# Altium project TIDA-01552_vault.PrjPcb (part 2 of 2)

## Sheet TIDA-01552_pg-5_OP_Connector.SchDoc
size 431 x 279 mm; Date: Not shown in title block; ApprovedBy: Not shown in title block; CheckedBy: Not shown in title block; Author: Not shown in title block; CompanyName: Not shown in title block; Engineer: Not shown in title block; Organization: Not shown in title block; Address1: Not shown in title block; Address2: Not shown in title block; Address3: Not shown in title block; Address4: Not shown in title block; DocumentNumber: 6; Revision: Use project parameter SCH_Rev; SheetNumber: 6; SheetTotal: 7; PageSetup: Record=PageOptions¦CenterHorizontal=True¦CenterVertical=True¦PrintScale=1.00¦XCorrection=1.00¦YCorrection=1.00¦PrintKind=0¦BorderSize=5000000¦LeftOffset=0¦BottomOffset=0¦Orientation=2¦PaperLength=1000¦PaperWidth=1000¦Scale=100¦PaperSource=15¦PrintQuality=600¦MediaType=1¦DitherType=10¦PaperKind=Letter¦PrintScaleMode=1
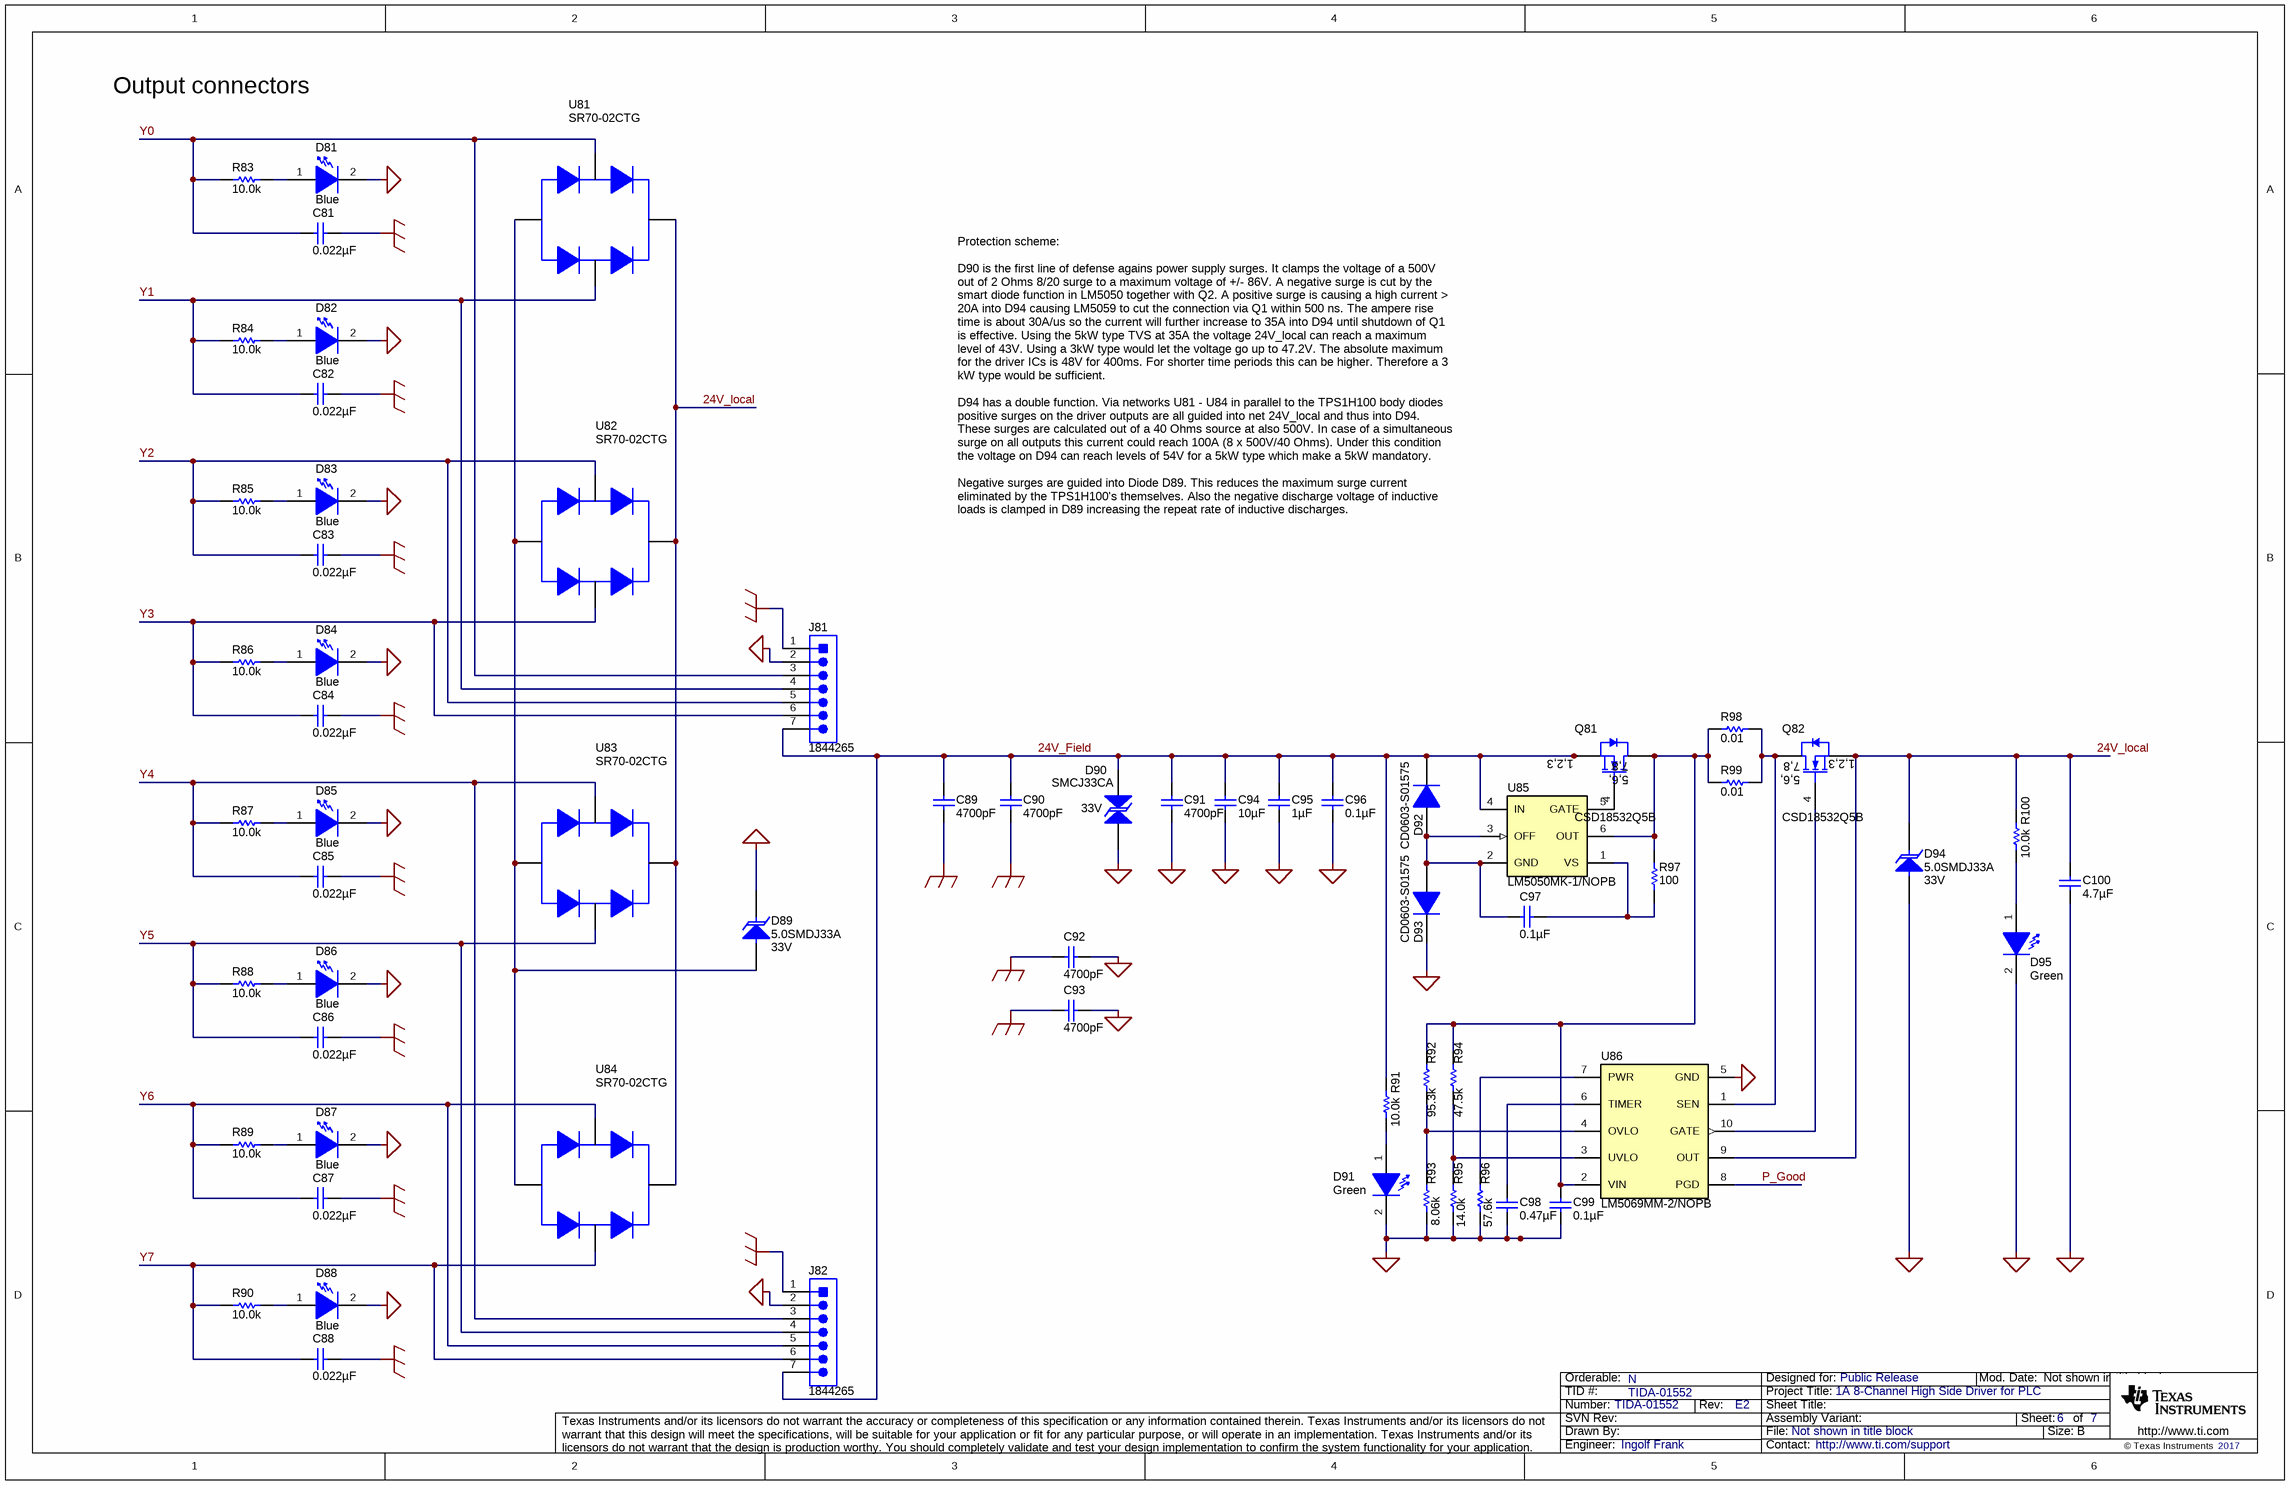
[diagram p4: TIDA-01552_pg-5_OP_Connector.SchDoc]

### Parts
C81  ValueDisplayed: 0.022µF  [0603]  (hidden comment: C1608X7R2A223K080AA)
C82  ValueDisplayed: 0.022µF  [0603]  (hidden comment: C1608X7R2A223K080AA)
C83  ValueDisplayed: 0.022µF  [0603]  (hidden comment: C1608X7R2A223K080AA)
C84  ValueDisplayed: 0.022µF  [0603]  (hidden comment: C1608X7R2A223K080AA)
C85  ValueDisplayed: 0.022µF  [0603]  (hidden comment: C1608X7R2A223K080AA)
C86  ValueDisplayed: 0.022µF  [0603]  (hidden comment: C1608X7R2A223K080AA)
C87  ValueDisplayed: 0.022µF  [0603]  (hidden comment: C1608X7R2A223K080AA)
C88  ValueDisplayed: 0.022µF  [0603]  (hidden comment: C1608X7R2A223K080AA)
C89  ValueDisplayed: 4700pF  [1812]  (hidden comment: 1812GC472KA1)
C90  ValueDisplayed: 4700pF  [1812]  (hidden comment: 1812GC472KA1)
C91  ValueDisplayed: 4700pF  [0805_HV]  (hidden comment: 08051C472KAT2A)
C92  ValueDisplayed: 4700pF  [1812]  (hidden comment: 1812GC472KA1)
C93  ValueDisplayed: 4700pF  [1812]  (hidden comment: 1812GC472KA1)
C94  ValueDisplayed: 10µF  [2220_250]  (hidden comment: C5750X7S2A106M230KB)
C95  ValueDisplayed: 1µF  [0805L]  (hidden comment: C2012X7S2A105K125AB)
C96  ValueDisplayed: 0.1µF  [0603]  (hidden comment: GRM188R72A104KA35D)
C97  ValueDisplayed: 0.1µF  [0603]  (hidden comment: GRM188R72A104KA35D)
C98  ValueDisplayed: 0.47µF  [0603]  (hidden comment: GRM188R71E474KA12D)
C99  ValueDisplayed: 0.1µF  [0603]  (hidden comment: GRM188R72A104KA35D)
C100  ValueDisplayed: 4.7µF  [1210_220]  (hidden comment: C3225X7S2A475K200AB)
D81  value Blue  [LB Q39G_BLUE]  (hidden comment: LB Q39G-L2N2-35-1)
D82  value Blue  [LB Q39G_BLUE]  (hidden comment: LB Q39G-L2N2-35-1)
D83  value Blue  [LB Q39G_BLUE]  (hidden comment: LB Q39G-L2N2-35-1)
D84  value Blue  [LB Q39G_BLUE]  (hidden comment: LB Q39G-L2N2-35-1)
D85  value Blue  [LB Q39G_BLUE]  (hidden comment: LB Q39G-L2N2-35-1)
D86  value Blue  [LB Q39G_BLUE]  (hidden comment: LB Q39G-L2N2-35-1)
D87  value Blue  [LB Q39G_BLUE]  (hidden comment: LB Q39G-L2N2-35-1)
D88  value Blue  [LB Q39G_BLUE]  (hidden comment: LB Q39G-L2N2-35-1)
D89  5.0SMDJ33A  value 33V  [SMC]
D90  SMCJ33CA  value 33V  [SMC]
D91  value Green  [LED_LTST-C190_G]  (hidden comment: LTST-C190KGKT)
D92  CD0603-S01575  [Diode_0603]
D93  CD0603-S01575  [Diode_0603]
D94  5.0SMDJ33A  value 33V  [SMC]
D95  value Green  [LED_LTST-C190_G]  (hidden comment: LTST-C190KGKT)
J81  1844265  [Phoenix_1844265]
J82  1844265  [Phoenix_1844265]
Q81  CSD18532Q5B  [DNK0008A]
Q82  CSD18532Q5B  [DNK0008A]
R83  value 10.0k  [0603]  (hidden comment: CRCW060310K0FKEA)
R84  value 10.0k  [0603]  (hidden comment: CRCW060310K0FKEA)
R85  value 10.0k  [0603]  (hidden comment: CRCW060310K0FKEA)
R86  value 10.0k  [0603]  (hidden comment: CRCW060310K0FKEA)
R87  value 10.0k  [0603]  (hidden comment: CRCW060310K0FKEA)
R88  value 10.0k  [0603]  (hidden comment: CRCW060310K0FKEA)
R89  value 10.0k  [0603]  (hidden comment: CRCW060310K0FKEA)
R90  value 10.0k  [0603]  (hidden comment: CRCW060310K0FKEA)
R91  value 10.0k  [0603]  (hidden comment: CRCW060310K0FKEA)
R92  value 95.3k  [0603_HV]  (hidden comment: CRCW060395K3FKEA)
R93  value 8.06k  [0603_HV]  (hidden comment: CRCW06038K06FKEA)
R94  value 47.5k  [0603_HV]  (hidden comment: CRCW060347K5FKEA)
R95  value 14.0k  [0603_HV]  (hidden comment: CRCW060314K0FKEA)
R96  value 57.6k  [0603_HV]  (hidden comment: CRCW060357K6FKEA)
R97  value 100  [0603]  (hidden comment: CRCW0603100RFKEA)
R98  value 0.01  [1206]  (hidden comment: WSLP1206R0100FEA)
R99  value 0.01  [1206]  (hidden comment: WSLP1206R0100FEA)
R100  value 10.0k  [0603]  (hidden comment: CRCW060310K0FKEA)
U81  SR70-02CTG  [SOT-143-4]
U82  SR70-02CTG  [SOT-143-4]
U83  SR70-02CTG  [SOT-143-4]
U84  SR70-02CTG  [SOT-143-4]
U85  LM5050MK-1/NOPB  [DDC0006A_N]
U86  LM5069MM-2/NOPB  [MUB10A_N]

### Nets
24V_local: C100.1 D94.1(K) Q82.1(S) Q82.2(S) Q82.3(S) R100.1 U81.4(VCC) U82.4(VCC) U83.4(VCC) U84.4(VCC) U86.9(OUT)
GND_EARTH: C81.2 C82.2 C83.2 C84.2 C85.2 C86.2 C87.2 C88.2 C89.2 C90.2 C92.2 C93.2 J81.1 J82.1
GND_SIGNAL: C91.2 C92.1 C93.1 C94.2 C95.2 C96.2 C98.2 C99.2 C100.2 D81.2(K) D82.2(K) D83.2(K) D84.2(K) D85.2(K) D86.2(K) D87.2(K) D88.2(K) D89.1(K) D90.2 D91.2(K) D93.1(K) D94.2(A) D95.2(K) J81.2 J82.2 R93.1 R95.1 R96.1 U86.5(GND)
24V_Field: C89.1 C90.1 C91.1 C94.1 C95.1 C96.1 D90.1 D92.1(K) J81.7 J82.7 Q81.1(S) Q81.2(S) Q81.3(S) R91.1 U85.4(IN)
P_Good: U86.8(PGD)
Y0: C81.1 J81.3 R83.2 U81.2(I/O)
Y1: C82.1 J81.4 R84.2 U81.3(I/O)
Y2: C83.1 J81.5 R85.2 U82.2(I/O)
Y3: C84.1 J81.6 R86.2 U82.3(I/O)
Y4: C85.1 J82.3 R87.2 U83.2(I/O)
Y5: C86.1 J82.4 R88.2 U83.3(I/O)
Y6: C87.1 J82.5 R89.2 U84.2(I/O)
Y7: C88.1 J82.6 R90.2 U84.3(I/O)
NetC97_1: C97.1 R97.1 U85.1(VS)
NetC97_2: C97.2 D92.2(A) D93.2(A) U85.2(GND) U85.3(OFF)
NetC98_1: C98.1 U86.6(TIMER)
NetC99_1: C99.1 Q81.5(D) Q81.6(D) Q81.7(D) Q81.8(D) Q81.9(D) R92.2 R94.2 R97.2 R98.1 R99.1 U85.6(OUT) U86.2(VIN)
NetD81_1: D81.1(A) R83.1
NetD82_1: D82.1(A) R84.1
NetD83_1: D83.1(A) R85.1
NetD84_1: D84.1(A) R86.1
NetD85_1: D85.1(A) R87.1
NetD86_1: D86.1(A) R88.1
NetD87_1: D87.1(A) R89.1
NetD88_1: D88.1(A) R90.1
NetD89_2: D89.2(A) U81.1(GND) U82.1(GND) U83.1(GND) U84.1(GND)
NetD91_1: D91.1(A) R91.2
NetD95_1: D95.1(A) R100.2
NetQ81_4: Q81.4(G) U85.5(GATE)
NetQ82_4: Q82.4(G) U86.10(GATE)
NetQ82_5: Q82.5(D) Q82.6(D) Q82.7(D) Q82.8(D) Q82.9(D) R98.2 R99.2 U86.1(SEN)
NetR92_1: R92.1 R93.2 U86.4(OVLO)
NetR94_1: R94.1 R95.2 U86.3(UVLO)
NetR96_2: R96.2 U86.7(PWR)

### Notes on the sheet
- Output connectors
- Protection scheme:
  D90 is the first line of defense agains power supply surges. It clamps the voltage of a 500V out of 2 Ohms 8/20 surge to a maximum voltage of +/- 86V. A negative surge is cut by the smart diode function in LM5050 together with Q2. A positive surge is causing a high current > 20A into D94 causing LM5059 to cut the connection via Q1 within 500 ns. The ampere rise time is about 30A/us so the current will further increase to 35A into D94 until shutdown of Q1 is effective. Using the 5kW type TVS at 35A the voltage 24V_local can reach a maximum level of 43V. Using a 3kW type would let the voltage go up to 47.2V. The absolute maximum for the driver ICs is 48V for 400ms. For shorter time periods this can be higher. Therefore a 3 kW type would be sufficient.
  D94 has a double function. Via networks U81 - U84 in parallel to the TPS1H100 body diodes positive surges on the driver outputs are all guided into net 24V_local and thus into D94. These surges are calculated out of a 40 Ohms source at also 500V. In case of a simultaneous surge on all outputs this current could reach 100A (8 x 500V/40 Ohms). Under this condition the voltage on D94 can reach levels of 54V for a 5kW type which make a 5kW mandatory.
  Negative surges are guided into Diode D89. This reduces the maximum surge current eliminated by the TPS1H100's themselves. Also the negative discharge voltage of inductive loads is clamped in D89 increasing the repeat rate of inductive discharges.

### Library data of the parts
C81-C88 = C1608X7R2A223K080AA: CAP, CERM, 0.022 µF, 100 V,+/- 10%, X7R, 0603; Manufacturer: TDK; Polarized: N; CompType: Capacitor; Value: 0.022uF; U/M: EA; Cap_F: 0.000000022; Tolerance_%: 10; ESR_ohm: 0.037; Value1: 0.037 ohm; VDC_V: 100; Value2: 100V; TaMin_C: -55; TaMax_C: 125; SizeArea_mm2: 1.28; SizeAreaWB_mm2: 4.68; SizeX_mm: 1.6; SizeY_mm: 0.8; SizeZ_mm: 1; AEC Category: Q200; Green_Lifecycle: Active; Green_REACh: Passed
C89 C90 C92 C93 = 1812GC472KA1: CAP, CERM, 4700 pF, 2000 V, +/- 10%, X7R, 1812; Manufacturer: AVX; Polarized: N; CompType: Capacitor; Value: 4700pF; U/M: EA; Cap_F: 0.0000000047; Tolerance_%: 10; Value1: Unknown; VDC_V: 2000; Value2: 2000V; TaMin_C: -55; TaMax_C: 125
C91 = 08051C472KAT2A: CAP, CERM, 4700 pF, 100 V,+/- 10%, X7R, 0805; Manufacturer: AVX; Polarized: N; CompType: Capacitor; Value: 4700pF; U/M: EA; Cap_F: 0.0000000047; Tolerance_%: 10; ESR_ohm: 0.119; Value1: 0.119 ohm; VDC_V: 100; Value2: 100V; TaMin_C: -55; TaMax_C: 125; Cap_Case: 0805; SizeArea_mm2: 2.5; SizeAreaWB_mm2: 6.75; SizeX_mm: 2; SizeY_mm: 1.25; SizeZ_mm: 1.45; AEC Category: Q200; Green_Lifecycle: Active; Green_REACh: Passed
C94 = C5750X7S2A106M230KB: CAP, CERM, 10 µF, 100 V,+/- 20%, X7S, 2220; Manufacturer: TDK; Polarized: N; CompType: Capacitor; Value: 10uF; U/M: EA; Cap_F: 0.00001; Tolerance_%: 20; ESR_ohm: 0.005; Value1: 0.005 ohm; VDC_V: 100; Value2: 100V; IRMS_A: 6.45; TaMin_C: -55; TaMax_C: 125; Cap_Case: 2220; SizeArea_mm2: 28.5; SizeAreaWB_mm2: 53.9; SizeX_mm: 5.7; SizeY_mm: 5; SizeZ_mm: 2.5; AEC Category: Q200; Green_Lifecycle: Active; Green_REACh: Passed
C95 = C2012X7S2A105K125AB: CAP, CERM, 1 µF, 100 V,+/- 10%, X7S, 0805; Manufacturer: TDK; Polarized: N; CompType: Capacitor; Value: 1uF; U/M: EA; Cap_F: 0.000001; Tolerance_%: 10; ESR_ohm: 0.008255; Value1: 0.008255 ohm; VDC_V: 100; Value2: 100V; IRMS_A: 2.27442; TaMin_C: -55; TaMax_C: 125; Cap_Case: 0805; SizeArea_mm2: 2.5; SizeAreaWB_mm2: 6.75; SizeX_mm: 2; SizeY_mm: 1.25; SizeZ_mm: 1.45; AEC Category: Q200; Green_Lifecycle: Active; Green_REACh: Passed
C96 C97 C99 = GRM188R72A104KA35D: CAP, CERM, 0.1 µF, 100 V, +/- 10%, X7R, 0603; Manufacturer: MuRata; Polarized: N; CompType: Capacitor; Value: 0.1uF; U/M: EA; Cap_F: 0.0000001; Tolerance_%: 10; Value1: Unknown; VDC_V: 100; Value2: 100V; TaMin_C: -55; TaMax_C: 125
C98 = GRM188R71E474KA12D: CAP, CERM, 0.47 µF, 25 V, +/- 10%, X7R, 0603; Manufacturer: MuRata; Polarized: N; CompType: Capacitor; Value: 0.47uF; Cap_F: 0.00000047; Tolerance_%: 10; VDC_V: 25; Value2: 25V; U/M: EA; Value1: Unknown; TaMin_C: -55; TaMax_C: 125
C100 = C3225X7S2A475K200AB: CAP, CERM, 4.7 µF, 100 V,+/- 10%, X7S, 1210; Manufacturer: TDK; Polarized: N; CompType: Capacitor; Value: 4.7uF; U/M: EA; Cap_F: 0.0000047; Tolerance_%: 10; ESR_ohm: 0.004236; Value1: 0.004236 ohm; VDC_V: 100; Value2: 100V; IRMS_A: 3.57337; TaMin_C: -55; TaMax_C: 125; Cap_Case: 1210; SizeArea_mm2: 8; SizeAreaWB_mm2: 14.7; SizeX_mm: 3.2; SizeY_mm: 2.5; SizeZ_mm: 2.2; AEC Category: Q200; Green_Lifecycle: Active; Green_REACh: Passed
D81-D88 = LB Q39G-L2N2-35-1: LED, Blue, SMD; Manufacturer: OSRAM; Vf_V: 2.85; Value2: 2.85V; Io_A: 0.15; Tjmax_C: 95; Value1: W; U/M: EA
D89 D94 = 5.0SMDJ33A: Diode, TVS, Uni, 33 V, 5000 W, SMC; Manufacturer: Littelfuse; U/M: EA; Power_W: 6.5; Vr_V: 33; Value1: 6.5W; RJA_CperW: 75
D90 = SMCJ33CA: Diode, TVS, Bi, 33V, 1500W, SMC; Manufacturer: Bourns; U/M: EA; Power_W: 1500; Vr_V: 33
D91 D95 = LTST-C190KGKT: LED, Green, SMD; Manufacturer: Lite-On; Type: AlInGaP; Vf_V: 2; Value2: 2V; Io_A: 0.03; Tjmax_C: 85; Value1: W; U/M: EA
D92 D93 = CD0603-S01575: Diode, Switching, 100 V, 0.15 A, 0603 Diode; Manufacturer: Bourns; U/M: EA; Vf_V: 1; Value: 100V; Value1: 0.15A; Value2: 1V; Io_A: 0.15; Vr_V: 100; TJmax_C: 125
J81 J82 = 1844265: Header (Shrouded), 3.5 mm, 7x1, R/A, TH; Manufacturer: Phoenix Contact; Alternate PartNumber: MC 1,5/ 7-G-3,5; SymbolCreator: a0411947; U/M: EA
Q81 Q82 = CSD18532Q5B: MOSFET, N-CH, 60 V, 172 A, DNK0008A (VSON-CLIP-8); Manufacturer: Texas Instruments; Alternate Manufacturer: None; U/M: EA; ChType: N; Value: 60V; VdsMax_V: 60; Value1: 3.3 ohm; Rdson45_ohm: 3.3; Value2: 27 nC; QgTyp_nC: 27; Vgs_V: 1.6; IdsMax_A: 172; SizeAreaWB_mm2: 56; SizeArea_mm2: 30; SizeX_mm: 6; SizeY_mm: 5; SizeZ_mm: 1; AEC Category: Q101
R83-R91 R100 = CRCW060310K0FKEA: RES, 10.0k ohm, 1%, 0.1W, 0603; Manufacturer: Vishay-Dale; CompType: Resistor; Res_ohm: 10000; Value_Code: 10k0; Tolerance_%: 1; Power_W: 0.1; VDC_V: 75; TempCo: 100 ppm/C; EIA_Code: E96; U/M: EA
R92 = CRCW060395K3FKEA: RES, 95.3k ohm, 1%, 0.1W, 0603; Manufacturer: Vishay-Dale; CompType: Resistor; Res_ohm: 95300; Value_Code: 95k3; Tolerance_%: 1; Power_W: 0.1; VDC_V: 75; TempCo: 100 ppm/C; EIA_Code: E96; U/M: EA
R93 = CRCW06038K06FKEA: RES, 8.06k ohm, 1%, 0.1W, 0603; Manufacturer: Vishay-Dale; CompType: Resistor; Res_ohm: 8060; Value_Code: 8k06; Tolerance_%: 1; Power_W: 0.1; VDC_V: 75; TempCo: 100 ppm/C; EIA_Code: E96; U/M: EA
R94 = CRCW060347K5FKEA: RES, 47.5k ohm, 1%, 0.1W, 0603; Manufacturer: Vishay-Dale; CompType: Resistor; Res_ohm: 47500; Value_Code: 47k5; Tolerance_%: 1; Power_W: 0.1; VDC_V: 75; TempCo: 100 ppm/C; EIA_Code: E96; U/M: EA
R95 = CRCW060314K0FKEA: RES, 14.0k ohm, 1%, 0.1W, 0603; Manufacturer: Vishay-Dale; CompType: Resistor; Res_ohm: 14000; Value_Code: 14k0; Tolerance_%: 1; Power_W: 0.1; VDC_V: 75; TempCo: 100 ppm/C; EIA_Code: E96; U/M: EA
R96 = CRCW060357K6FKEA: RES, 57.6k ohm, 1%, 0.1W, 0603; Manufacturer: Vishay-Dale; CompType: Resistor; Res_ohm: 57600; Value_Code: 57k6; Tolerance_%: 1; Power_W: 0.1; VDC_V: 75; TempCo: 100 ppm/C; EIA_Code: E96; U/M: EA
R97 = CRCW0603100RFKEA: RES, 100 ohm, 1%, 0.1W, 0603; Manufacturer: Vishay-Dale; CompType: Resistor; Value_Code: 100R; Tolerance_%: 1; Power_W: 0.1; VDC_V: 75; TempCo: 100 ppm/C; EIA_Code: E96; U/M: EA
R98 R99 = WSLP1206R0100FEA: RES, 0.01 ohm, 1%, 1W, 1206; Manufacturer: Vishay-Dale; CompType: Resistor; Value_Code: R010; Tolerance_%: 1; TempCo: 75 ppm/C; EIA_Code: E96; U/M: EA
U81-U84 = SR70-02CTG: ESD Suppressor Diode Arrays, 70V, SMD; Manufacturer: Littelfuse; SymbolCreator: Altium; CompType: ESD Diode Array
U85 = LM5050MK-1/NOPB: LM5050-1 High Side OR-ing FET Controller, DDC0006A; Alternate Manufacturer: None; Manufacturer: Texas Instruments; SymbolCreator: a0411947; CompType: IC; U/M: EA
U86 = LM5069MM-2/NOPB: Positive High Voltage Hot Swap / Inrush Current Controller with Power Limiting, 10-pin MSOP, Pb-Free; Manufacturer: National Semiconductor; PackageTopMarking: ZXTT*SNBB; PowerWise: N; CompType: MiscPower

## Sheet TIDA-01552_TID_Hardware.SchDoc
size 431 x 279 mm; Date: Not shown in title block; ApprovedBy: Not shown in title block; CheckedBy: Not shown in title block; Author: Not shown in title block; CompanyName: Not shown in title block; Engineer: Not shown in title block; Organization: Not shown in title block; Address1: Not shown in title block; Address2: Not shown in title block; Address3: Not shown in title block; Address4: Not shown in title block; DocumentNumber: 7; Revision: Use project parameter SCH_Rev; SheetNumber: 7; SheetTotal: 7; PageSetup: Record=PageOptions¦CenterHorizontal=True¦CenterVertical=True¦PrintScale=1.00¦XCorrection=1.00¦YCorrection=1.00¦PrintKind=0¦BorderSize=5000000¦LeftOffset=0¦BottomOffset=0¦Orientation=2¦PaperLength=1000¦PaperWidth=1000¦Scale=100¦PaperSource=15¦PrintQuality=600¦MediaType=1¦DitherType=10¦PaperKind=Letter¦PrintScaleMode=1
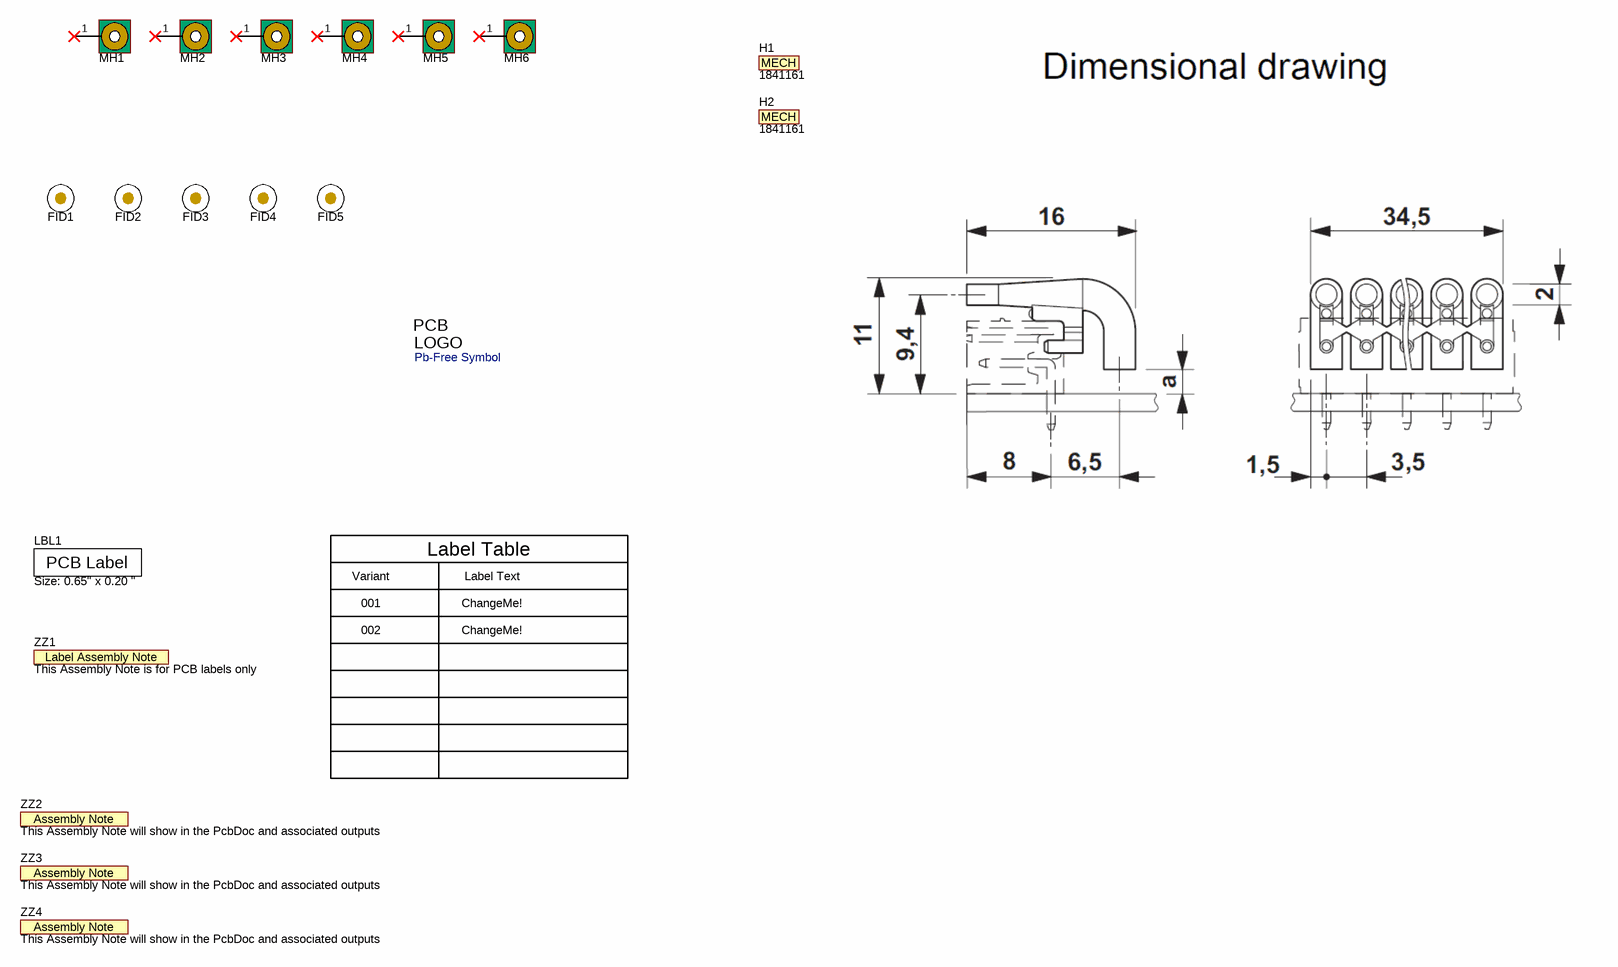
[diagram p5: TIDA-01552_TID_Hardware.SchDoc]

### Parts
FID1  Fiducial  [Fiducial10-20]  (value not drawn)
FID2  Fiducial  [Fiducial10-20]  (value not drawn)
FID3  Fiducial  [Fiducial10-20]  (value not drawn)
FID4  Fiducial  [Fiducial10-20]  (value not drawn)
FID5  Fiducial  [Fiducial10-20]  (value not drawn)
H1  1841161  (mechanical)
H2  1841161  (mechanical)
LBL1  Size: 0.65" x 0.20 "  [Label_650x200]
Logo2  Pb-Free Symbol  [Pb-Free_Overlay_Small]  (no BOM)
MH1  MTG_Pads  [MTGP_4-40_PanHead]  (value not drawn)  (no BOM)
MH2  MTG_Pads  [MTGP_4-40_PanHead]  (value not drawn)  (no BOM)
MH3  MTG_Pads  [MTGP_4-40_PanHead]  (value not drawn)  (no BOM)
MH4  MTG_Pads  [MTGP_4-40_PanHead]  (value not drawn)  (no BOM)
MH5  MTG_Pads  [MTGP_4-40_PanHead]  (value not drawn)  (no BOM)
MH6  MTG_Pads  [MTGP_4-40_PanHead]  (value not drawn)  (no BOM)
ZZ1  This Assembly Note is for PCB labels only  [AssemblyNoteLabel]  (no BOM)
ZZ2  This Assembly Note will show in the PcbDoc and associated outputs  [AssemblyNote]  (no BOM)
ZZ3  This Assembly Note will show in the PcbDoc and associated outputs  [AssemblyNote]  (no BOM)
ZZ4  This Assembly Note will show in the PcbDoc and associated outputs  [AssemblyNote]  (no BOM)

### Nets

Not connected (* = marked no-connect by the designer): MH1 1*; MH2 1*; MH3 1*; MH4 1*; MH5 1*; MH6 1*

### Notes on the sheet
- Variant
- Label Table
- Label Text
- 001
- 002
- ChangeMe!

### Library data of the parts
FID1-FID5 = Fiducial: Fiducial mark.  There is nothing to buy or mount.; SymbolCreator: codlsc
H1 H2 = 1841161: Fiber optics - MC 1,5/10-LWL 1,5-3,5 for Phoenix connectors; Manufacturer: Phoenix Contact; SymbolCreator: codlsc; CompType: Filber Optics
LBL1 = THT-14-423-10: Thermal Transfer Printable Labels, 0.650" W x 0.200" H - 10,000 per roll; Manufacturer: Brady; SymbolCreator: a0412235; CompType: Label
Logo2 = Pb-Free: SymbolCreator: a0412235
MH1-MH6 = Mounting Hole (Imperial) with Pads: PCB Mounting Hole; Manufacturer: Any; SymbolCreator: a0412235
ZZ1 = AssemblyNoteLabel: SymbolCreator: a0412235
ZZ2-ZZ4 = AssemblyNote: SymbolCreator: codlsc

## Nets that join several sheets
24V_local: TIDA-01552_pg-2_PSU-ISO (L21.1), TIDA-01552_pg-4_Driver (33 pins), TIDA-01552_pg-5_OP_Connector (11 pins)
+3.3V_iso: TIDA-01552_pg-2_PSU-ISO (10 pins), TIDA-01552_pg-3_MCU (12 pins), TIDA-01552_pg-4_Driver (C63.1 U63.1 U63.9 U63.14)
DGND: TIDA-01552_pg-1_BB_Connector (30 pins), TIDA-01552_pg-2_PSU-ISO (10 pins)
GND_SIGNAL: TIDA-01552_pg-2_PSU-ISO (19 pins), TIDA-01552_pg-3_MCU (15 pins), TIDA-01552_pg-4_Driver (38 pins), TIDA-01552_pg-5_OP_Connector (29 pins)
SYS_5V: TIDA-01552_pg-1_BB_Connector (J2.7 J2.8 S1.1), TIDA-01552_pg-2_PSU-ISO (C31.1 T21.5 U25.2)
VDD_3V3B: TIDA-01552_pg-1_BB_Connector (24 pins), TIDA-01552_pg-2_PSU-ISO (8 pins)
/CS0: TIDA-01552_pg-1_BB_Connector (R6.2), TIDA-01552_pg-2_PSU-ISO (U22.5)
/CS0_iso: TIDA-01552_pg-2_PSU-ISO (R25.1), TIDA-01552_pg-3_MCU (U44.9)
/SDRDY: TIDA-01552_pg-2_PSU-ISO (U21.7), TIDA-01552_pg-3_MCU (U44.18)
/XSDRDY: TIDA-01552_pg-1_BB_Connector (R1.2), TIDA-01552_pg-2_PSU-ISO (R21.1 U26.4)
CSense: TIDA-01552_pg-3_MCU (U44.7), TIDA-01552_pg-4_Driver (C69.1 R81.1 TP64.1)
D0: TIDA-01552_pg-3_MCU (U44.15), TIDA-01552_pg-4_Driver (R63.1)
D1: TIDA-01552_pg-3_MCU (U44.16), TIDA-01552_pg-4_Driver (R64.1)
D2: TIDA-01552_pg-3_MCU (U44.32), TIDA-01552_pg-4_Driver (R68.1)
D3: TIDA-01552_pg-3_MCU (U44.19), TIDA-01552_pg-4_Driver (R69.1)
D4: TIDA-01552_pg-3_MCU (U44.21), TIDA-01552_pg-4_Driver (R73.1)
D5: TIDA-01552_pg-3_MCU (U44.3), TIDA-01552_pg-4_Driver (R74.1)
D6: TIDA-01552_pg-3_MCU (U44.23), TIDA-01552_pg-4_Driver (R78.1)
D7: TIDA-01552_pg-3_MCU (U44.24), TIDA-01552_pg-4_Driver (R79.1)
MISO: TIDA-01552_pg-1_BB_Connector (R7.2), TIDA-01552_pg-2_PSU-ISO (R26.2)
MISO_iso: TIDA-01552_pg-2_PSU-ISO (U22.11), TIDA-01552_pg-3_MCU (R43.1)
MOSI: TIDA-01552_pg-1_BB_Connector (R3.2), TIDA-01552_pg-2_PSU-ISO (U22.3)
MOSI_iso: TIDA-01552_pg-2_PSU-ISO (R23.1), TIDA-01552_pg-3_MCU (U44.10)
P_Good: TIDA-01552_pg-3_MCU (R46.2 U44.2), TIDA-01552_pg-5_OP_Connector (U86.8)
RST_n: TIDA-01552_pg-2_PSU-ISO (U21.6), TIDA-01552_pg-3_MCU (U45.2)
SCLK: TIDA-01552_pg-1_BB_Connector (R5.2), TIDA-01552_pg-2_PSU-ISO (U22.4)
SCLK_iso: TIDA-01552_pg-2_PSU-ISO (R24.1), TIDA-01552_pg-3_MCU (U44.12)
ShiftCLK: TIDA-01552_pg-3_MCU (R65.1), TIDA-01552_pg-4_Driver (TP61.1 U63.8)
ShiftSTRT: TIDA-01552_pg-3_MCU (R45.2 U44.22), TIDA-01552_pg-4_Driver (U63.2)
Supply_div: TIDA-01552_pg-3_MCU (U44.6), TIDA-01552_pg-4_Driver (C66.1 R72.1 R75.2 TP62.1)
XRST_n: TIDA-01552_pg-1_BB_Connector (R2.2), TIDA-01552_pg-2_PSU-ISO (R22.1 U21.3)
Y0: TIDA-01552_pg-4_Driver (U69.5 U69.6 U69.7), TIDA-01552_pg-5_OP_Connector (C81.1 J81.3 R83.2 U81.2)
Y1: TIDA-01552_pg-4_Driver (U68.5 U68.6 U68.7), TIDA-01552_pg-5_OP_Connector (C82.1 J81.4 R84.2 U81.3)
Y2: TIDA-01552_pg-4_Driver (U67.5 U67.6 U67.7), TIDA-01552_pg-5_OP_Connector (C83.1 J81.5 R85.2 U82.2)
Y3: TIDA-01552_pg-4_Driver (U66.5 U66.6 U66.7), TIDA-01552_pg-5_OP_Connector (C84.1 J81.6 R86.2 U82.3)
Y4: TIDA-01552_pg-4_Driver (U65.5 U65.6 U65.7), TIDA-01552_pg-5_OP_Connector (C85.1 J82.3 R87.2 U83.2)
Y5: TIDA-01552_pg-4_Driver (U64.5 U64.6 U64.7), TIDA-01552_pg-5_OP_Connector (C86.1 J82.4 R88.2 U83.3)
Y6: TIDA-01552_pg-4_Driver (U62.5 U62.6 U62.7), TIDA-01552_pg-5_OP_Connector (C87.1 J82.5 R89.2 U84.2)
Y7: TIDA-01552_pg-4_Driver (U61.5 U61.6 U61.7), TIDA-01552_pg-5_OP_Connector (C88.1 J82.6 R90.2 U84.3)

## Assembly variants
001: all parts fitted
